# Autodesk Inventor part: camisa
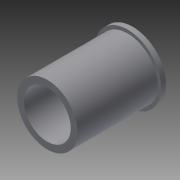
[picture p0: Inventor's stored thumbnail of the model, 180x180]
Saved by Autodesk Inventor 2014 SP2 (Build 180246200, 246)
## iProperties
Created: 2016-04
Part Number: camisa
Material: Genérico
Document SubType Name: Modeling
Designer: Celiberto
Density: 1 g/cm^3
Appearance: Padrão
Mass: 2.65307 g
Surface Area: 28.9341 cm^2
Volume: 2.65307 cm^3
Author: Celiberto
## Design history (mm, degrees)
sketch "Esboço1"
  geometry: C1 r 9 at (0, 0); 1 further point
  constraints: 1 centre point, 1 coincident
  dimensions: "d0" = 18 diameter of C1
extrude "Extrusão1" new body sketch "Esboço1" distance "d1" = 25.5; taper "d2" = 0 deg
sketch "Esboço2"
  geometry: C1 r 9 at (0, 0) reference; C2 r 10 at (0, 0)
  constraints: 1 centre point, 1 coincident
  dimensions: "d3" = 20 diameter of C2
extrude "Extrusão2" join sketch "Esboço2" distance "d4" = 1.5; taper "d5" = 0 deg
sketch "Esboço3"
  geometry: C1 r 10 at (0, 0) reference; C2 r 7 at (0, 0)
  constraints: 1 centre point, 1 coincident
  dimensions: "d6" = 14 diameter of C2
extrude "Extrusão3" cut sketch "Esboço3" distance "d7" = 38; taper "d8" = 0 deg
sketch "Esboço4"
  geometry: C1 r 9 at (0, 0) reference; C2 r 7 at (0, 0)
  constraints: 1 centre point, 1 coincident
  dimensions: "d9" = 14 diameter of C2
extrude "Extrusão4" cut sketch "Esboço4" distance "d10" = 33.5; taper "d11" = 0 deg
node "Sólido1"
